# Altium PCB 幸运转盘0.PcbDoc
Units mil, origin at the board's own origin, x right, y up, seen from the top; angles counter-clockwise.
Board outline 2362.2 x 2362.2 mil, 2 copper layers (Top Layer, Bottom Layer); 22 components, 17 nets, 67 pads, 0 vias.
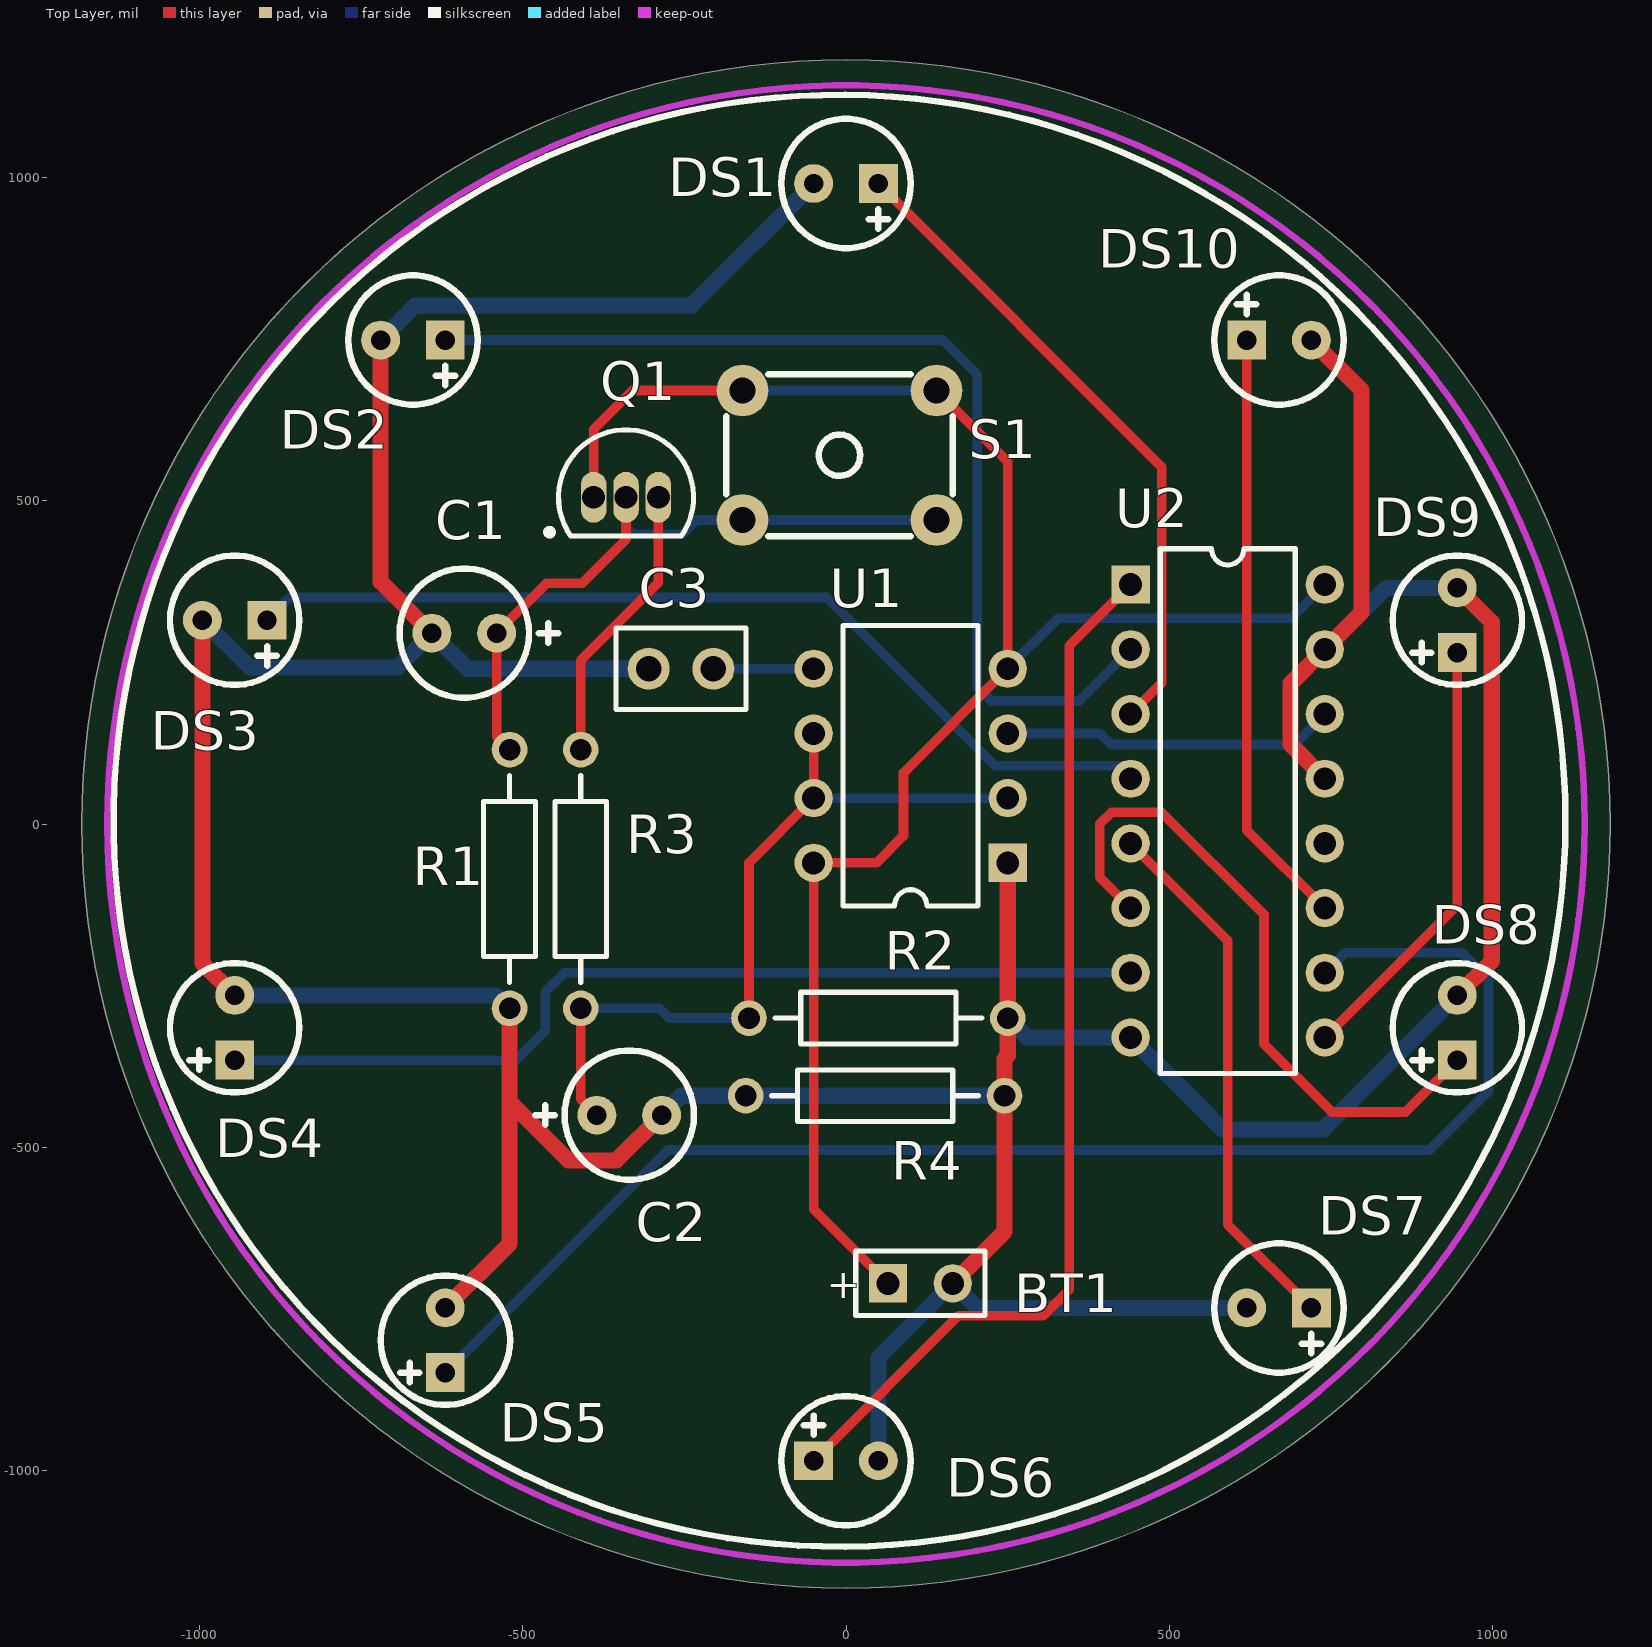
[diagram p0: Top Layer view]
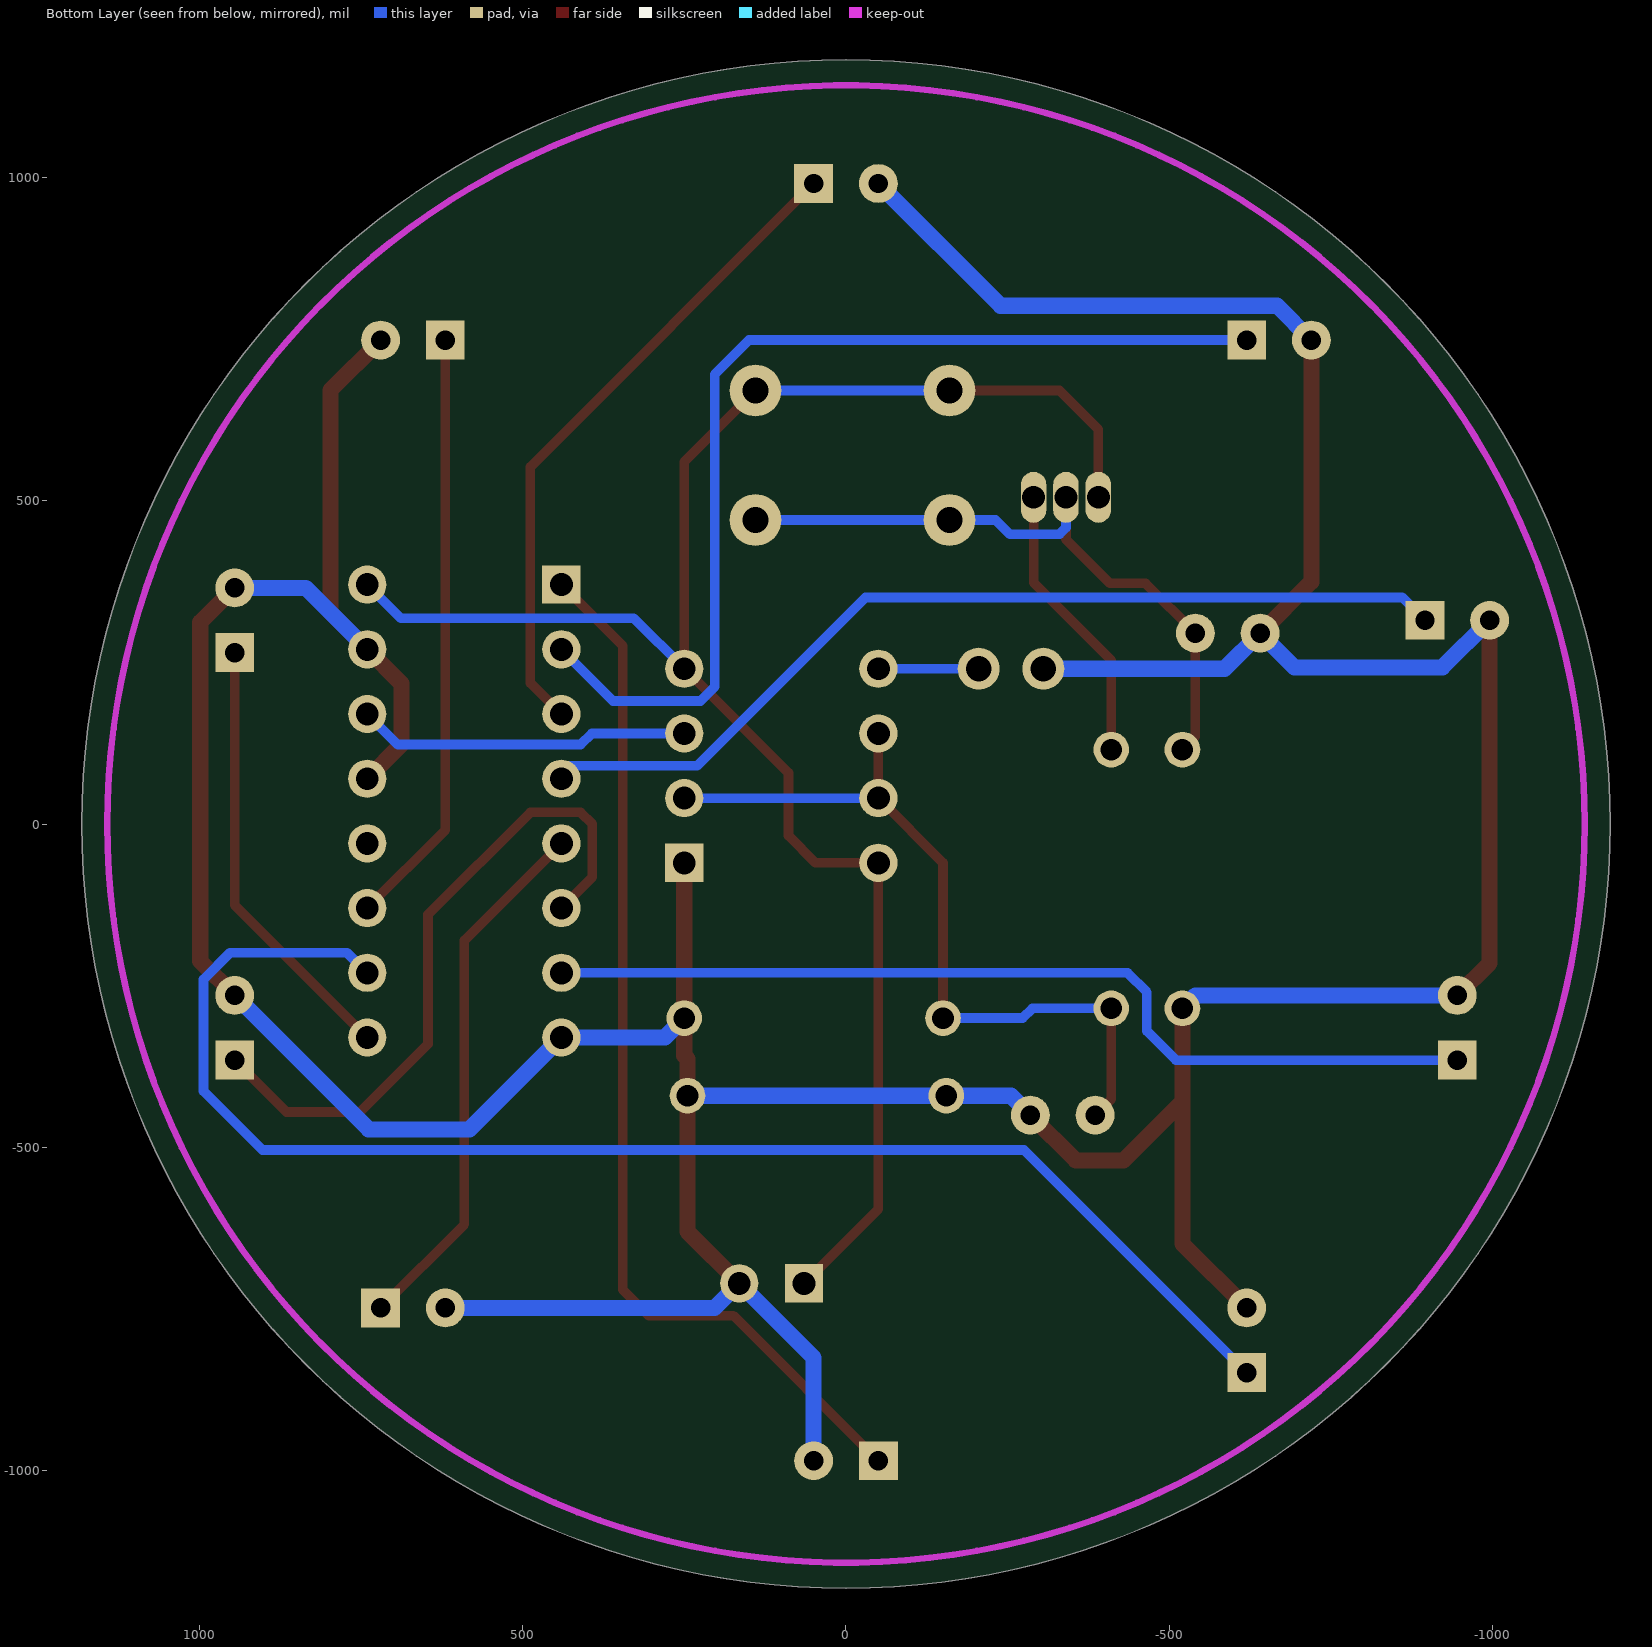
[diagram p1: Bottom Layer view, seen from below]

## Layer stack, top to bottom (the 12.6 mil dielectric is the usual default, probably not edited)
Top Solder: solder mask 0.4, Solder Resist, Dk 3.5
Top Layer: signal copper 1.4
Dielectric 1: dielectric 12.6, FR-4, Dk 4.8
Bottom Layer: signal copper 1.4
Bottom Solder: solder mask 0.4, Solder Resist, Dk 3.5

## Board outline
-1181.1,0 ccw(c0,0) 0,-1181.1 ccw(c0,0) 1181.1,0 ccw(c0,0) 0,1181.1 ccw(c0,0)

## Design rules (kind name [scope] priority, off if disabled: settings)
Clearance [All] p1: gap=10
MinimumSolderMaskSliver [All] p1: minsoldermaskwidth=1
PolygonConnect [All] p1: connectstyle=Relief reliefconductorwidth=10 reliefentries=4 polygonreliefangle="90 Angle" airgapwidth=10
RoutingVias [All] p1: holewidth=28 width=50 viastyle="Through Hole" minholewidth=28 minwidth=50 maxholewidth=28 maxwidth=50
SilkToSilkClearance [All] p1: silktosilkclearance=1
SilkToSolderMaskClearance [IsPad] p1: minsilkscreentomaskgap=1 clearancetoexposedcopper=TRUE
SolderMaskExpansion [All] p1: expansion=4
Width GND [InNet('GND')] p1: maxlimit=25 minlimit=10 preferedwidth=25
Width [All] p2: maxlimit=15 minlimit=10 preferedwidth=15
27 further rules are at their usual default settings.

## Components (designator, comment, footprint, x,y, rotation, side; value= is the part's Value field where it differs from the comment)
BT1 "Battery" BAT-2 115,-710 r0 top
C1 "Cap Pol2" 电解电容-100uF -590,295 r180 top
C2 "Cap Pol2" 电解电容-100uF -335,-450 r0 top
C3 "Cap" CAPR2.54-5.1X3.2 -255,240 r180 top
DS1 "LED0" 发光二极管 0,990 r180 top
DS2 "LED0" 发光二极管 -669.29,748.03 r180 top
DS3 "LED0" 发光二极管 -944.88,314.96 r180 top
DS4 "LED0" 发光二极管 -944.88,-314.96 r90 top
DS5 "LED0" 发光二极管 -619.29,-798.03 r90 top
DS6 "LED0" 发光二极管 0,-984.25 r0 top
DS7 "LED0" 发光二极管 669.29,-748.03 r180 top
DS8 "LED0" 发光二极管 944.88,-314.96 r90 top
DS9 "LED0" 发光二极管 944.88,314.96 r90 top
DS10 "LED0" 发光二极管 669.29,748.03 r0 top
Q1 "NPN" TO-226-AA -340,505 r270 top
R1 "Res2" AXIAL-0.4 -520,-85 r90 top
R2 "Res2" AXIAL-0.4 50,-300 r180 top
R3 "Res2" AXIAL-0.4 -410,-85 r90 top
R4 "Res2" AXIAL-0.4 45,-420 r0 top
S1 "SW-PB" 轻触开关 -10,570 r180 top
U1 "NE555N" DIP8 100,90 r90 top
U2 "CD4017BCN" N16E 590,20 r270 top

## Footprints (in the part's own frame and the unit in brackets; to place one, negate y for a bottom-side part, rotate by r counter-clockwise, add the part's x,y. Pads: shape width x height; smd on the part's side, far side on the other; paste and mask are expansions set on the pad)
AXIAL-0.4 [mm] "Axial Device, Thru-Hole; 2 Leads; 0.4 in Pin Spacing"
  round 1.4 hole 0.85: 1(-5.08,0) 2(5.08,0)
  silkscreen extent -4.06,-1.02 4.06,1.02
BAT-2 [mm] "Battery; 2 Leads"
  rect 1.5x1.5 hole 0.9: 1(-1.27,0)
  round 1.5 hole 0.9: 2(1.27,0)
  silkscreen extent -2.54,-1.27 2.54,1.27
CAPR2.54-5.1X3.2 [mm]
  round 1.65 hole 1: 1(-1.27,0) 2(1.27,0)
  silkscreen extent -2.55,-1.6 2.55,1.6
DIP8 [mm] "DIP; 8 Leads; Row Spacing 7.62 mm; Pitch 2.54 mm"
  rect 1.5x1.5 hole 0.9: 1(-3.81,-3.81)
  round 1.5 hole 0.9: 2(-1.27,-3.81) 3(1.27,-3.81) 4(3.81,-3.81) 5(3.81,3.81) 6(1.27,3.81) 7(-1.27,3.81) 8(-3.81,3.81)
  silkscreen extent -5.5,-2.65 5.5,2.65
N16E [mm] "DIP; 16 Leads; Row Spacing 7.62 mm; Pitch 2.54 mm"
  rect 1.5x1.5 hole 0.9: 1(-8.89,-3.81)
  round 1.5 hole 0.9: 2(-6.35,-3.81) 3(-3.81,-3.81) 4(-1.27,-3.81) 5(1.27,-3.81) 6(3.81,-3.81) 7(6.35,-3.81) 8(8.89,-3.81) 9(8.89,3.81) 10(6.35,3.81) 11(3.81,3.81) 12(1.27,3.81) 13(-1.27,3.81) 14(-3.81,3.81) 15(-6.35,3.81) 16(-8.89,3.81)
  silkscreen extent -10.3,-2.65 10.3,2.65
TO-226-AA [mm] "TO, Flat Index; 3 In-Line, Axial Leads; Body Dia. 4.8mm; Leads 0.55 x 0.51 mm (max)"
  oval 2x1 hole 0.9: 1(0,-1.27) 2(0,0) 3(0,1.27)
  silkscreen extent -2.65,-3.13 1.52,2.65, body extent -2.65,-2.66 1.52,2.66, height 5.33
发光二极管 [mil]
  rect 60x60 hole 30: 1(-50,0)
  round 60 hole 30: 2(50,0)
  silkscreen extent -100,-100 100,100
电解电容-100uF [mil]
  round 60 hole 30: 1(-50,0) 2(50,0)
  silkscreen extent -145,-100 100,100
轻触开关 [mil]
  round 80 hole 40: 1(-150,100) 1(150,100) 2(-150,-100) 2(150,-100)
  silkscreen extent -175,-125 175,125

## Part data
BT1: "Multicell Battery"
C1 C2: "Polarized Capacitor (Axial)"
C3: "Capacitor"
DS1 DS2 DS3 DS4 DS5 DS6 DS7 DS8 DS9 DS10: "Typical INFRARED GaAs LED"
Q1: "NPN Bipolar Transistor"
R1 R2 R3 R4: "Resistor"
S1: "Switch"
U1: "General-Purpose Single Bipolar Timer"
U2: "Decade Counter/Divider with 10 Decoded Outputs"

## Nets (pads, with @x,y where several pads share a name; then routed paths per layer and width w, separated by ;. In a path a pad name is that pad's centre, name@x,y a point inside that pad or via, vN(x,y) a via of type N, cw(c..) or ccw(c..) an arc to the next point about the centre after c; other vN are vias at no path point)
GND: BT1.2 C1.2 C2.2 C3.2 DS1.2 DS2.2 DS3.2 DS4.2 DS5.2 DS6.2 DS7.2 DS8.2 DS9.2 DS10.2 R1.1 R2.1 R4.1 R4.2 U1.1 U2.8 U2.13 U2.15 | length 8427.2
  Top Layer w25: DS3.2 -994.88,-214.96 DS4.2 ; DS2.2 -719.29,374.29 C1.2 ; DS5.2 -520,-648.74 -520,-429 ; R1.1 -520,-429 ; C2.2 -355,-520 -429,-520 -520,-429 ; BT1.2 245,-630 R4.2 245,-363 250,-358 R2.1 U1.1 ; DS10.2 797,670.32 797,327 U2.15 687,217 687,123 U2.13 ; DS8.2 998,-211.84 998,311.84 DS9.2
  Bottom Layer w25: DS3.2 -921.92,242 -693,242 C1.2 -585,240 C3.2 ; DS4.2 -540.04,-264.96 R1.1 ; DS2.2 -666.32,801 -239,801 DS1.2 ; C2.2 -255,-420 R4.1 R4.2 ; DS6.2 50,-825 BT1.2 203.03,-748.03 DS7.2 ; R2.1 280,-330 U2.8 582,-472 737.84,-472 DS8.2 ; U2.15 834.96,364.96 DS9.2
NetBT1_1: BT1.1 Q1.1 S1.2 U1.4 U1.8 U2.16 | length 2858
  Top Layer w15: Q1.1 -390,610 -330,670 S1.2@-160,670 ; BT1.1 -50,-595 U1.8 47,-60 89,-18 89,79 U1.4 250,560 S1.2@140,670
  Bottom Layer w15: S1.2@-160,670 S1.2@140,670 ; U1.4 328,318 688,318 U2.16
NetC1_1: C1.1 Q1.2 R1.2 S1.1 | length 1053.6
  Top Layer w15: R1.2 -540,135 C1.1 -463,372 -408,372 -340,440 Q1.2
  Bottom Layer w15: Q1.2 -340,458 -330,448 -253,448 -231,470 -160,470 S1.1@140,470
NetC2_1: C2.1 R2.2 R3.1 U1.2 U1.6 U1.7 | length 1223
  Top Layer w15: R3.1 -410,-425 C2.1 ; R2.2 -150,-60 U1.7 U1.6
  Bottom Layer w15: R3.1 -288,-285 -273,-300 R2.2 ; U1.7 U1.2
NetC3_1: C3.1 U1.5 | length 155
  Bottom Layer w15: C3.1 U1.5
NetDS1_1: DS1.1 U2.3 | length 1021.3
  Top Layer w15: DS1.1 488,552 488,218 U2.3
NetDS2_1: DS2.1 U2.2 | length 1606.5
  Bottom Layer w15: DS2.1 150,748.03 202.97,695.06 202.97,212.03 225,190 360,190 U2.2
NetDS3_1: DS3.1 U2.4 | length 1477.1
  Bottom Layer w15: DS3.1 -859.84,350 -30,350 230,90 440,90 U2.4
NetDS4_1: DS4.1 U2.7 | length 1475.9
  Bottom Layer w15: DS4.1 -509.96,-364.96 -465,-320 -465,-260 -435,-230 U2.7
NetDS5_1: DS5.1 U2.10 | length 2248.3
  Bottom Layer w15: DS5.1 -275.26,-504 902,-504 993,-413 993,-240 952,-199 771,-199 U2.10
NetDS6_1: DS6.1 U2.1 | length 1633.8
  Top Layer w15: DS6.1 174.25,-760 305,-760 345,-720 345,275 U2.1
NetDS7_1: DS7.1 U2.5 | length 833.7
  Top Layer w15: U2.5 590,-180 590,-618.74 DS7.1
NetDS8_1: DS8.1 U2.6 | length 1052.3
  Top Layer w15: U2.6 392,-82 392,0 410,18 488,18 646,-140 646,-340 751,-445 864.84,-445 DS8.1
NetDS9_1: DS9.1 U2.9 | length 679.8
  Top Layer w15: U2.9 944.88,-125.12 DS9.1
NetDS10_1: DS10.1 U2.11 | length 928
  Top Layer w15: DS10.1 619.29,-9.29 U2.11
NetQ1_3: Q1.3 R3.2 | length 439.7
  Top Layer w15: R3.2 -410,253 -290,373 Q1.3
NetU1_3: U1.3 U2.14 | length 516.5
  Bottom Layer w15: U1.3 392.97,140 410,122.97 692.97,122.97 U2.14
pads on no net: U2.12

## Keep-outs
Keep-Out Layer:
  circle w10: c0,0 r1141.73

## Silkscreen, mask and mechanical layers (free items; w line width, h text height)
Top Overlay:
  circle w10: c-10,5 r1122.05
Mechanical 1:
  circle w10: c0,0 r1181.1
